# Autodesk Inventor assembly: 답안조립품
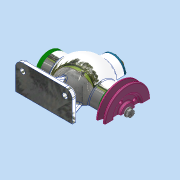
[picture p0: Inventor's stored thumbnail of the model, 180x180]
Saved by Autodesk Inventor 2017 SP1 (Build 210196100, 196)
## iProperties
Part Number: 답안조립품
Material: 일반
Document SubType Name: Assembly
Designer: MRC
Author: MRC
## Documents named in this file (16)
- C:\Users\MRC\Desktop\720811V1011\답안조립품.iam
- C:\Users\MRC\Desktop\720811V1011\본체.ipt
- C:\Users\MRC\Desktop\720811V1011\V-벨트풀리.ipt
- C:\Users\MRC\Desktop\720811V1011\너트 M8.ipt
- C:\Users\MRC\Desktop\720811V1011\뒤커버.ipt
- C:\Users\MRC\Desktop\720811V1011\베어링- 6202.ipt
- KS B 2023 - 6202 - 15 x 35 x 11 - 7.8.ipt
- C:\Users\MRC\Desktop\720811V1011\볼트 M4 x 12.ipt
- C:\Users\MRC\Desktop\720811V1011\볼트 M4 x 16.ipt
- C:\Users\MRC\Desktop\720811V1011\상부커버.ipt
- C:\Users\MRC\Desktop\720811V1011\슬라이드.ipt
- C:\Users\MRC\Desktop\720811V1011\앞커버.ipt
- C:\Users\MRC\Desktop\720811V1011\오일실 15 30 7.ipt
- C:\Users\MRC\Desktop\720811V1011\칼라.ipt
- C:\Users\MRC\Desktop\720811V1011\키 4 x 4 x 12.ipt
- C:\Users\MRC\Desktop\720811V1011\편심축.ipt
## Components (15 placed, 4 different names)
1. V-벨트풀리:1
2. KS B 2023 - 6202 - 15 x 35 x 11 - 7.8:1
3. KS B 2023 - 6202 - 15 x 35 x 11 - 7.8:2
4. ISO 4762 M4 x 16:1
5. ISO 4762 M4 x 16:3
6. ISO 4762 M4 x 16:4
7. ISO 4762 M4 x 16:5
8. ISO 4762 M4 x 16:2
9. ISO 4762 M4 x 16:6
10. ISO 4762 M4 x 16:7
11. ISO 4762 M4 x 16:8
12. KS B 1021 - 에 따름 ISO 1207 - 미터 A  M 4 x 12:1
13. KS B 1021 - 에 따름 ISO 1207 - 미터 A  M 4 x 12:2
14. KS B 1021 - 에 따름 ISO 1207 - 미터 A  M 4 x 12:3
15. KS B 1021 - 에 따름 ISO 1207 - 미터 A  M 4 x 12:4
